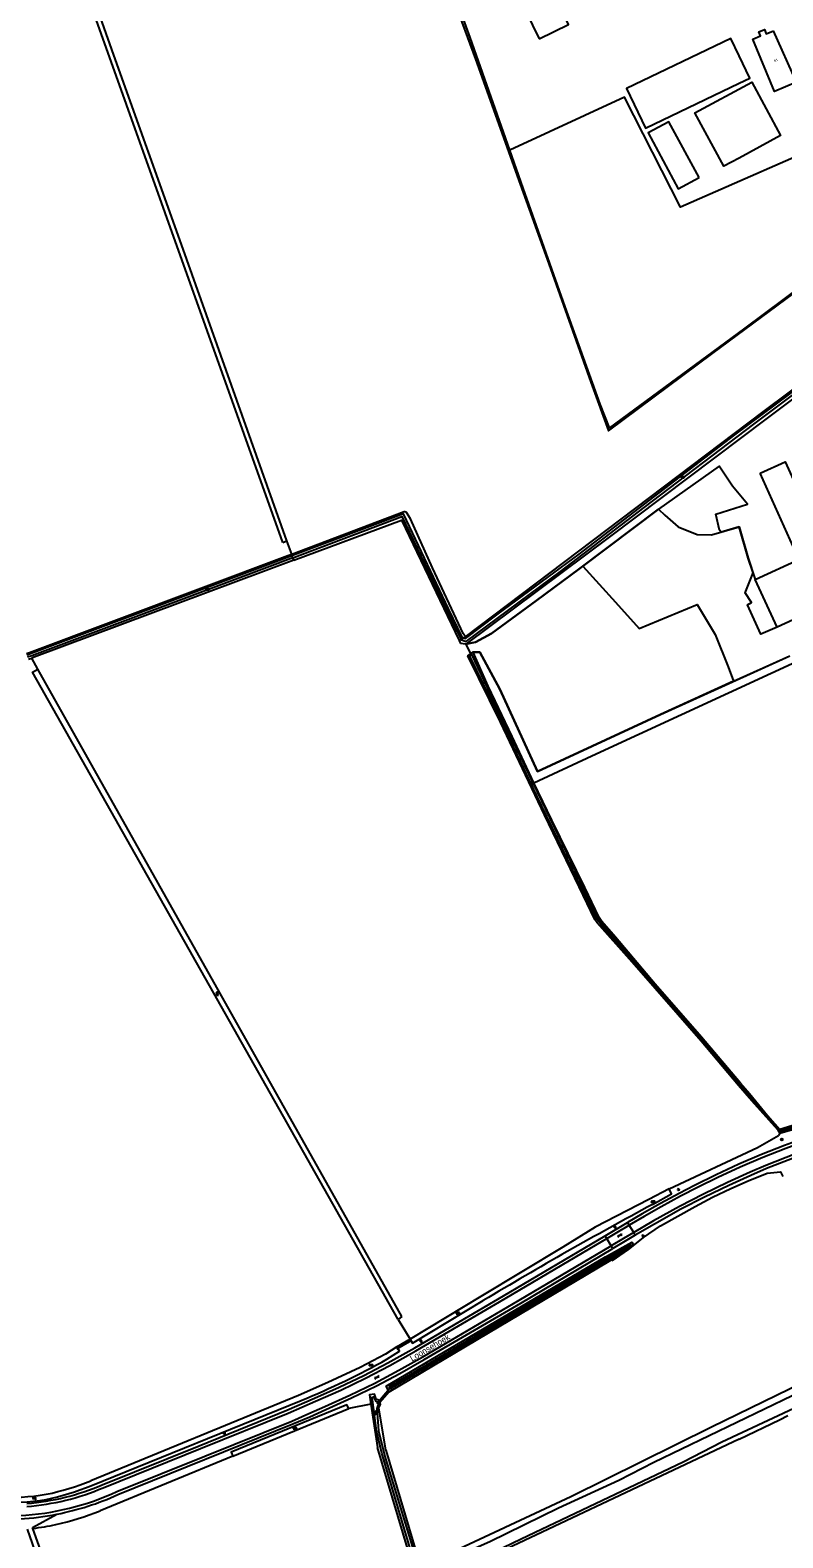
# Model space of a CAD drawing. Extents: x 134297 to 137000, y 403500 to 406000.
# Drawn here: x 135711 to 136018, y 404322 to 404935 of the extents above; entities that cross this region are included whole.
import ezdxf

# ---------------------------------------------------------------- set-up
doc = ezdxf.new("R2010")
doc.units = 0
for name, color, linetype in [('gg-afsc-erfafscheiding', 7, 'Continuous'), ('gg-afsc-lijn draadraster', 7, 'Continuous'), ('gg-anno-huisnummerreeks BGT', 7, 'Continuous'), ('gg-anno-openbare ruimte label', 7, 'Continuous'), ('gg-bbg-gedigitaliseerde bebouwing', 7, 'Continuous'), ('gg-bbg-gedigitaliseerde bijgebouw', 7, 'Continuous'), ('gg-bbg-hoofdgebouw', 7, 'Continuous'), ('gg-bbg-open loods', 7, 'Continuous'), ('gg-knt-bronhoudergrens', 7, 'Continuous'), ('gg-knt-onverhard', 7, 'Continuous'), ('gg-knt-verharding', 7, 'Continuous'), ('gg-knt-verharding nz', 7, 'Continuous'), ('gg-kntw-bovenkant insteek waterloop', 7, 'Continuous'), ('gg-kntw-greppel-droge sloot', 7, 'Continuous'), ('gg-kntw-waterlijn', 7, 'Continuous'), ('gg-kwrk-duiker nz buis', 7, 'Continuous'), ('gt-grn-groengrens', 7, 'Continuous'), ('gt-grn-vlakafsluiter', 7, 'Continuous'), ('gt-symb-boom', 7, 'Continuous'), ('gt-symb-gesloten verharding', 7, 'Continuous'), ('gt-symb-groenvak', 7, 'Continuous'), ('gt-symb-lichtmast', 7, 'Continuous'), ('gt-symb-watersymbool', 7, 'Continuous')]:
    doc.layers.add(name, color=color, linetype=linetype)

# ---------------------------------------------------------------- blocks, each defined once
blk = doc.blocks.new('gt0-WA')
at = {"layer": 'gt-symb-watersymbool'}
for centre, start, end in [((-0.32, 0.02), 28.07249, 151.92751), ((0.43, 0.42), 208.07248, 331.92751), ((-0.32, -0.43), 28.07249, 151.92751), ((0.43, -0.03), 208.07248, 331.92751)]:
    blk.add_arc(centre, 0.425, start, end, dxfattribs=at)
blk = doc.blocks.new('gt0-GRVAK')
at = {"layer": 'gt-symb-groenvak'}
for p, q in [((-0.11, 0.19), (-0.23, 0.24)), ((-0.18, 0.15), (0.09, 0.15)), ((-0.09, 0.21), (-0.16, 0.32)), ((-0.05, 0.21), (-0.05, 0.39)), ((0, 0.21), (0.06, 0.32)), ((0.01, 0.19), (0.13, 0.24)), ((0.26, -0.05), (0.2, 0.06)), ((0.3, -0.05), (0.3, 0.13)), ((0.35, -0.05), (0.41, 0.06)), ((-0.24, -0.23), (-0.36, -0.18)), ((-0.32, -0.26), (-0.05, -0.26)), ((-0.23, -0.21), (-0.29, -0.09)), ((-0.18, -0.2), (-0.18, -0.02)), ((-0.14, -0.21), (-0.07, -0.09)), ((-0.12, -0.23), (0, -0.18)), ((0.24, -0.07), (0.12, -0.02)), ((0.17, -0.11), (0.44, -0.11)), ((0.37, -0.07), (0.49, -0.02))]:
    blk.add_line(p, q, dxfattribs=at)
blk = doc.blocks.new('gt0-BOOM')
at = {"layer": 'gt-symb-boom'}
for radius in [0.4, 0.2]:
    blk.add_circle((0, 0), radius, dxfattribs=at)
blk = doc.blocks.new('gt0-LMAST')
at = {"layer": 'gt-symb-lichtmast'}
for p, q in [((-0.18, 0.17), (-0.45, 0.44)), ((-0.01, 0.25), (-0.01, 0.62)), ((0.17, 0.17), (0.44, 0.44)), ((-0.26, 0), (-0.63, 0)), ((-0.18, -0.18), (-0.45, -0.45)), ((-0.01, -0.25), (-0.01, -0.63)), ((0.44, -0.45), (0.17, -0.18)), ((0.24, 0), (0.62, 0))]:
    blk.add_line(p, q, dxfattribs=at)
blk.add_circle((-0.01, 0), 0.25, dxfattribs=at)
blk = doc.blocks.new('gt0-GESVH1')
at = {"layer": 'gt-symb-gesloten verharding'}
for p, q in [((-0.99, -0.26), (0.01, 0.24)), ((0.01, -0.26), (-0.99, 0.24)), ((0.01, 0.24), (1.01, -0.26)), ((1.01, 0.24), (0.01, -0.26))]:
    blk.add_line(p, q, dxfattribs=at)

msp = doc.modelspace()

# ---------------------------------------------------------------- linework, layer by layer
at = {"layer": 'gg-afsc-erfafscheiding'}
for points in [[(135957.54, 404441.04), (135961.12, 404443.87), (135967.97, 404448.6), (135982.07, 404456.53), (135989.17, 404460.21), (135996.7, 404463.84), (136003.68, 404466.94), (136011.43, 404470.04), (136016.83, 404470.55), (136017.86, 404468.65)], [(135948.32, 404434.33), (135954.91, 404438.96), (135957.54, 404441.04)]]:
    msp.add_lwpolyline(points, dxfattribs=at)
at = {"layer": 'gg-afsc-lijn draadraster'}
for points in [[(135888.71, 404685.35), (135892.64, 404686.27), (135899.22, 404689.69), (135917.56, 404703.22), (135934.71, 404715.88), (135967.23, 404740.38), (135969.71, 404737.86), (135975.2, 404733.09), (135982.87, 404730), (135988.76, 404729.87), (136000.04, 404733.1), (136003.69, 404720.35), (136006.61, 404711.76)], [(135891.63, 404682.14), (135894.48, 404682.14), (135902.55, 404667.01), (135917.87, 404633.54), (135968.02, 404656.71), (136020.74, 404680.69)]]:
    msp.add_lwpolyline(points, dxfattribs=at)
at = {"layer": 'gg-bbg-gedigitaliseerde bebouwing'}
for p, q in [((136015.5, 404692.32), (136006.61, 404711.76)), ((136037.55, 404702.41), (136015.5, 404692.32))]:
    msp.add_line(p, q, dxfattribs=at)
for points in [[(136023.43, 404914.15), (136014.49, 404910.31), (136005.64, 404931.74), (136008.69, 404933), (136007.99, 404934.68), (136010.3, 404935.64), (136011.03, 404933.86), (136014.05, 404935.11)], [(136006.61, 404711.76), (136043.23, 404728.51), (136050.86, 404711.82)]]:
    msp.add_lwpolyline(points, dxfattribs=at)
at = {"layer": 'gg-bbg-gedigitaliseerde bijgebouw'}
for points in [[(135918.59, 404931.82), (135930.48, 404937.6), (135922.33, 404954.36), (135910.45, 404948.58), (135918.59, 404931.82)], [(136000, 404913.71), (136004.38, 404915.8), (136000, 404924.86), (135996.62, 404931.93), (135954.14, 404911.6), (135961.86, 404895.46), (136000, 404913.71)], [(136000, 404883.29), (135993.79, 404879.94), (135982.05, 404901.68), (136005.16, 404914.15), (136016.9, 404892.42), (136000, 404883.29)], [(135983.69, 404875.3), (135971.4, 404898.07), (135962.95, 404893.51), (135975.24, 404870.74), (135983.69, 404875.3)]]:
    msp.add_lwpolyline(points, dxfattribs=at)
at = {"layer": 'gg-bbg-hoofdgebouw'}
msp.add_line((136023.43, 404914.15), (136014.05, 404935.11), dxfattribs=at)
at = {"layer": 'gg-bbg-open loods'}
msp.add_lwpolyline([(136008.58, 404755.04), (136018.79, 404759.66), (136032.3, 404729.75), (136022.09, 404725.14), (136008.58, 404755.04)], dxfattribs=at)
at = {"layer": 'gg-knt-bronhoudergrens'}
for p, q in [((135817.78, 404721.99), (135815.85, 404727.41)), ((135888.71, 404685.35), (135890.62, 404681.43)), ((135714.42, 404675.26), (135711.91, 404679.73)), ((135997.78, 404670.3), (136020.74, 404680.69)), ((135861.09, 404410.43), (135866.07, 404402.51))]:
    msp.add_line(p, q, dxfattribs=at)
for points in [[(136015.5, 404692.32), (136008.81, 404689.4), (136003.4, 404701.35), (136005.13, 404702.37), (136002.48, 404706.25), (136005.71, 404714.41), (136005.71, 404714.41), (136003.69, 404720.35), (136000.04, 404733.1), (135992.7, 404731), (135992.06, 404731.79), (135990.52, 404738.33), (136003.4, 404742.41), (135997.27, 404749.77), (135991.96, 404757.84), (135967.23, 404740.38), (135936.4, 404717.16)], [(135916.45, 404629), (135940.08, 404639.92), (136124.35, 404724.9)], [(135936.4, 404717.16), (135934.71, 404715.88), (135917.56, 404703.22), (135899.22, 404689.69), (135892.64, 404686.27), (135888.71, 404685.35)], [(135936.4, 404717.16), (135949.67, 404702.47), (135959.37, 404691.75), (135982.97, 404701.55), (135990.22, 404689.3), (135995.63, 404676.22), (135997.78, 404670.3)], [(135997.78, 404670.3), (135968.02, 404656.71), (135917.87, 404633.54), (135902.55, 404667.01), (135894.48, 404682.14), (135891.63, 404682.14)], [(135971.54, 404463.67), (136007.56, 404480.54), (136016.01, 404485.35)]]:
    msp.add_lwpolyline(points, dxfattribs=at)
at = {"layer": 'gg-knt-onverhard'}
for p, q in [((135712.18, 404325.82), (135722.09, 404331.22)), ((135722.25, 404291.15), (135710.12, 404325.06)), ((135712.31, 404325.45), (135712.18, 404325.82)), ((135724.39, 404292.09), (135712.31, 404325.45))]:
    msp.add_line(p, q, dxfattribs=at)
at = {"layer": 'gg-knt-verharding'}
for p, q in [((135945.45, 404444.58), (135954.61, 404449.98)), ((135955.27, 404448.86), (135954.61, 404449.98)), ((135957.08, 404445.86), (135955.27, 404448.86)), ((135957.74, 404444.76), (135957.08, 404445.86)), ((135946.12, 404443.45), (135945.45, 404444.58)), ((135947.92, 404440.47), (135946.12, 404443.45)), ((135948.58, 404439.37), (135947.92, 404440.47))]:
    msp.add_line(p, q, dxfattribs=at)
for points in [[(136197.49, 404535.45), (136195.13, 404534.58), (136162.9, 404522.97), (136127.36, 404510.1), (136113.62, 404505.3), (136099.76, 404500.63), (136086.34, 404496.28), (136076.86, 404493.32), (136066.07, 404490.19), (136055.56, 404487.24), (136045.09, 404484), (136034.7, 404480.64), (136023.56, 404476.68), (136011.23, 404471.9), (136004.74, 404469.15), (135995.87, 404465.09), (135985.92, 404460.27), (135976.35, 404455.35), (135965.54, 404449.33), (135957.74, 404444.76)], [(136108.2, 404509.87), (136098.64, 404506.63), (136084.48, 404502.05), (136070.65, 404497.79), (136060.14, 404494.87), (136049.92, 404491.85), (136039.52, 404488.61), (136028.95, 404485.07), (136018.55, 404481.26), (136009.16, 404477.58), (135999.86, 404473.65), (135990.66, 404469.37), (135981.82, 404465.02), (135975.54, 404461.77), (135967.96, 404457.68), (135960.58, 404453.48), (135954.61, 404449.98)], [(135740.54, 404343.18), (135780.12, 404359.11), (135815.76, 404373.51), (135827.08, 404378.39), (135837.06, 404382.9), (135847.16, 404387.74), (135856.95, 404392.79), (135867.93, 404398.96), (135904.12, 404420.16), (135945.45, 404444.58)], [(135746.93, 404339.17), (135818.29, 404367.99), (135825.14, 404370.92), (135831.67, 404373.79), (135842.2, 404378.57), (135852.33, 404383.49), (135861.87, 404388.55), (135871.74, 404394.13), (135911.08, 404417.16), (135948.58, 404439.37)], [(135957.74, 404444.76), (135953.56, 404442.31), (135948.58, 404439.37)]]:
    msp.add_lwpolyline(points, dxfattribs=at)
for centre, radius, start, end in [((135702.17, 404432.43), 97.15, 274.53281, 293.26455), ((135700.9, 404440.23), 111.05, 281.00014, 294.49037), ((135700.86, 404440.33), 111.16, 273.17752, 281.0098)]:
    msp.add_arc(centre, radius, start, end, dxfattribs=at)
at = {"layer": 'gg-knt-verharding nz'}
for points in [[(136197.15, 404540.4), (136161.45, 404527.53), (136124.76, 404514.25), (136111.52, 404509.6), (136099.13, 404505.43), (136084.9, 404500.78), (136071.52, 404496.67), (136060.9, 404493.69), (136050.35, 404490.61), (136039.81, 404487.34), (136029.4, 404483.84), (136019.03, 404480.06), (136009.73, 404476.4), (136000.5, 404472.45), (135991.4, 404468.23), (135983.33, 404464.29), (135976.2, 404460.63), (135968.25, 404456.35), (135961.29, 404452.4), (135955.27, 404448.86)], [(136197.38, 404536.83), (136126.86, 404511.31), (136112.69, 404506.32), (136099.4, 404501.86), (136086.05, 404497.55), (136076.48, 404494.56), (136065.87, 404491.48), (136055.28, 404488.5), (136044.76, 404485.25), (136034.33, 404481.86), (136023.04, 404477.86), (136010.9, 404473.14), (136004.49, 404470.44), (135995.36, 404466.29), (135985.46, 404461.47), (135975.71, 404456.46), (135965.21, 404450.62), (135957.08, 404445.86)], [(135946.12, 404443.45), (135950.24, 404445.9), (135955.27, 404448.86)], [(135957.08, 404445.86), (135952.93, 404443.43), (135947.92, 404440.47)], [(135741.02, 404342), (135780.57, 404357.93), (135816.37, 404372.36), (135827.53, 404377.18), (135837.73, 404381.77), (135847.78, 404386.58), (135857.7, 404391.73), (135868.35, 404397.7), (135904.76, 404419.01), (135939.21, 404439.35), (135946.12, 404443.45)], [(135746.53, 404340.42), (135782.41, 404354.84), (135817.78, 404369.15), (135824.75, 404372.15), (135831.32, 404375.02), (135841.52, 404379.66), (135851.6, 404384.58), (135861.4, 404389.8), (135871.13, 404395.29), (135910.38, 404418.29), (135947.92, 404440.47)]]:
    msp.add_lwpolyline(points, dxfattribs=at)
for centre, radius, start, end in [((135702.21, 404432.79), 98.73, 274.43036, 293.14082), ((135701.35, 404438.77), 108.23, 272.98533, 294.67638)]:
    msp.add_arc(centre, radius, start, end, dxfattribs=at)
at = {"layer": 'gg-kntw-bovenkant insteek waterloop'}
for p, q in [((135817.78, 404721.99), (135863.53, 404739.35)), ((135817.78, 404721.99), (135817.64, 404721.95)), ((135886.02, 404686.91), (135886.6, 404685.71)), ((135888.71, 404685.35), (135886.6, 404685.71)), ((135710.57, 404679.25), (135711.91, 404679.73)), ((135891.63, 404682.14), (135890.62, 404681.43)), ((135862.58, 404411.68), (135714.42, 404675.26)), ((136015.74, 404487.62), (136016.61, 404486.32)), ((135971.54, 404463.67), (135963.3, 404459.3)), ((135894.87, 404419.83), (135866.07, 404402.51)), ((135862.58, 404411.68), (135861.09, 404410.43)), ((135860.59, 404399.33), (135856.04, 404396.3)), ((135820.6, 404379.54), (135736.01, 404344.85)), ((135735.97, 404342.78), (135821.69, 404377.57)), ((135793.78, 404354.9), (135840.99, 404374.19)), ((135850.06, 404375.98), (135852.72, 404358.41)), ((136000, 404361.71), (136016.41, 404369.66)), ((136016.41, 404369.66), (136019.93, 404371.37)), ((135856.14, 404357.26), (135870.01, 404310.73))]:
    msp.add_line(p, q, dxfattribs=at)
for points in [[(135883.81, 404947.37), (135892.62, 404923.5), (135909.58, 404876.1), (135922.55, 404840.24), (135939.63, 404792.04), (135946.81, 404772.2), (135989.29, 404803.84), (136051.9, 404850.06)], [(135906.64, 404886.48), (135890.46, 404932.4), (135884.87, 404947.76)], [(136051.9, 404850.06), (136051.5, 404850.62), (136001.81, 404813.68), (135947.26, 404773.45), (135943.41, 404783.07), (135929.19, 404822.74), (135912.06, 404871.08), (135906.64, 404886.48)], [(135888.64, 404688.41), (136009.8, 404779.91), (136075.84, 404829.22)], [(136077.07, 404826.68), (136011.46, 404777.41), (135947.05, 404728.91), (135888.71, 404685.35)], [(135818.63, 404719.53), (135862.53, 404735.9), (135886.02, 404686.91)], [(135888.64, 404688.41), (135887.6, 404689.79), (135875.12, 404716.41), (135866.2, 404736.36), (135864.55, 404739.03), (135863.53, 404739.35)], [(135817.64, 404721.95), (135816.14, 404721.38), (135711.01, 404681.86), (135709.72, 404681.43)], [(135818.63, 404719.53), (135712.86, 404680.07), (135711.91, 404679.73)], [(135999.83, 404505.8), (135984.5, 404523.77), (135956.43, 404555.89), (135942.15, 404572.01), (135941.32, 404573.36), (135934.86, 404586.61), (135920.78, 404615.89), (135902.8, 404653.64), (135889.49, 404680.65), (135890.62, 404681.43)], [(135916.45, 404629), (135907.56, 404647.81), (135897.76, 404668.29), (135891.63, 404682.14)], [(135861.09, 404410.43), (135712.21, 404674.03), (135714.42, 404675.26)], [(136000.6, 404506.74), (135984.69, 404525.37), (135965.77, 404546.93), (135949.72, 404566.06), (135944.07, 404572.56), (135943.03, 404574.15), (135937.18, 404586.34), (135923.68, 404613.72), (135916.45, 404629)], [(136015.74, 404487.62), (136005.19, 404499.51), (135999.83, 404505.8)], [(136000.6, 404506.74), (136004.27, 404502.44), (136011.6, 404493.47), (136016.62, 404487.88)], [(136016.61, 404486.32), (136052.67, 404496.71), (136063.77, 404500)], [(136057.39, 404500), (136046.29, 404496.71), (136035.18, 404493.49), (136016.62, 404487.88)], [(136232.4, 404483.42), (136229.09, 404483.22), (136211.35, 404474.91), (136179.65, 404459.33), (136143.55, 404441.91), (136089.18, 404415.38), (136050.09, 404396.55), (136020.57, 404382.16), (135988.75, 404366.64), (135931.54, 404338.35), (135877.73, 404313.16)], [(135963.3, 404459.3), (135941.33, 404448.06), (135928.25, 404439.96), (135894.87, 404419.83)], [(135964.72, 404457.32), (135972.46, 404461.64), (135971.54, 404463.67)], [(135857.5, 404381.02), (135856.24, 404383.31), (135945.62, 404435.99), (135956.35, 404441.9), (135957.06, 404440.85)], [(135857.5, 404381.02), (135951.42, 404436.76), (135957.06, 404440.85)], [(135866.07, 404402.51), (135866.98, 404400.84), (135895.78, 404418.15)], [(135856.58, 404394.29), (135861.71, 404397.54), (135860.59, 404399.33)], [(135856.04, 404396.3), (135845.68, 404390.96), (135832.52, 404384.79), (135820.6, 404379.54)], [(135853.71, 404376.7), (135853.5, 404377.57), (135852.23, 404378.07), (135851.53, 404380.11), (135849.47, 404379.86), (135850.06, 404375.98)], [(135840.99, 404374.19), (135840.26, 404375.75), (135793.19, 404356.51), (135793.78, 404354.9)], [(135856.14, 404357.26), (135853.25, 404374.45), (135853.93, 404375.83), (135853.71, 404376.7)], [(136000, 404361.71), (135880.94, 404305.58), (135878.61, 404307.31), (135876.7, 404311.45), (135877.73, 404313.16)], [(135870.01, 404310.73), (135867.31, 404309.61), (135852.72, 404358.41)]]:
    msp.add_lwpolyline(points, dxfattribs=at)
for centre, radius, start, end in [((136796.91, 402911.99), 1755.16, 118.3033, 120.89196), ((135693.81, 404689.21), 336.86, 292.31094, 298.89416), ((135704.18, 404415.49), 77.37, 250.13401, 280.16042), ((135696.53, 404439.94), 104.86, 281.69302, 292.09406), ((135696.57, 404442.01), 104.86, 281.69302, 292.09406), ((135703.54, 404415.03), 79.07, 250.3395, 280.37058)]:
    msp.add_arc(centre, radius, start, end, dxfattribs=at)
at = {"layer": 'gg-kntw-greppel-droge sloot'}
for q in [(135721.84, 404985.18), (135815.85, 404727.41)]:
    msp.add_line((135814.21, 404726.79), q, dxfattribs=at)
msp.add_lwpolyline([(135815.85, 404727.41), (135772.93, 404848.03), (135745.3, 404925.2), (135724.03, 404985.56)], dxfattribs=at)
at = {"layer": 'gg-kntw-waterlijn'}
for points in [[(135886.83, 404687.37), (135886.94, 404687.16), (135888.8, 404686.46), (135927.31, 404715.02), (135961.33, 404741.08), (136005.98, 404775), (136059.04, 404814.65), (136071.15, 404823.52), (136076.55, 404827.75)], [(135887.78, 404687.92), (135888.53, 404687.75), (135901.38, 404697.31), (135934.87, 404722), (135998.34, 404770.55), (136076.18, 404828.52)], [(135887.78, 404687.92), (135887.4, 404688.01), (135881.62, 404699.74), (135863.31, 404738.4), (135817.87, 404721.38)], [(135818.22, 404720.54), (135862.7, 404737.4), (135882.82, 404695.13), (135886.83, 404687.37)], [(135817.87, 404721.38), (135723.6, 404686.07), (135709.89, 404680.98)], [(135818.22, 404720.54), (135797.39, 404712.64), (135711.87, 404680.62), (135710.23, 404680.11)], [(136000.05, 404506.07), (135985.86, 404522.72), (135952.19, 404561.37), (135944.49, 404570.16), (135942.3, 404573.14), (135936.29, 404585.2), (135917.69, 404623.61), (135898.57, 404663.48), (135890.32, 404680.57), (135891.08, 404681.2), (135904.09, 404653.8), (135933.18, 404593.08), (135942.65, 404573.73), (135944.11, 404571.66), (135979.04, 404531.32), (135989.04, 404519.72), (136000.35, 404506.45)], [(136016.73, 404487.35), (136022.35, 404489.09), (136076.78, 404505.34), (136106.63, 404514.78), (136106.73, 404514.04), (136081.04, 404505.97), (136016.77, 404486.75)], [(136016.77, 404486.75), (136014.83, 404489.08), (136000.05, 404506.07)], [(136000.35, 404506.45), (136005.99, 404499.83), (136011.37, 404493.32), (136016.73, 404487.35)], [(135884.16, 404313.75), (135898.53, 404320.11), (135926.42, 404333.8), (135951.05, 404345.14), (135965.34, 404352.44), (136021.67, 404379.51), (136084.87, 404410.41), (136126.48, 404430.96), (136169.18, 404451.47), (136204.36, 404468.59), (136233.6, 404482.32), (136235.31, 404482.99), (136237.37, 404483.02), (136237.66, 404482.34)], [(135885.33, 404308.76), (135911.22, 404321.24), (135977.2, 404352.57), (135993.05, 404360.74), (136022.28, 404374.43), (136052.47, 404388.81), (136081.4, 404402.63), (136112.63, 404418.58), (136144.64, 404434.05), (136190.99, 404456.03), (136224.47, 404472.11), (136236.59, 404477.67), (136237.28, 404476.11)], [(135857.42, 404383.07), (135871.82, 404391.44), (135955.81, 404441.14), (135956.05, 404440.74), (135950.12, 404436.93), (135930.56, 404425.27), (135857.86, 404382.2), (135857.42, 404383.07)], [(135867.78, 404311.24), (135854.48, 404356.01), (135852.34, 404365.16), (135850.49, 404378.87), (135851.08, 404378.95), (135851.86, 404377.38), (135852.68, 404376.98), (135853.09, 404376.23), (135852.4, 404374.19), (135853.16, 404365.1), (135855.75, 404354.71), (135868.92, 404311.61), (135867.78, 404311.24)]]:
    msp.add_lwpolyline(points, dxfattribs=at)
at = {"layer": 'gg-kwrk-duiker nz buis'}
for p, q in [((135860.66, 404398.53), (135866.72, 404402)), ((135857.65, 404382.25), (135852.4, 404376.19))]:
    msp.add_line(p, q, dxfattribs=at)
at = {"layer": 'gt-grn-groengrens'}
for p, q in [((136016.61, 404486.32), (136016.01, 404485.35)), ((135957.54, 404441.04), (135957.06, 404440.85)), ((135865.27, 404402.05), (135866.07, 404402.51)), ((135860.59, 404399.33), (135865.27, 404402.05)), ((135857.5, 404381.02), (135853.71, 404376.7)), ((135850.06, 404375.98), (135840.99, 404374.19)), ((135793.78, 404354.9), (135739.76, 404332.65))]:
    msp.add_line(p, q, dxfattribs=at)
msp.add_lwpolyline([(136045.86, 404893.83), (136043.08, 404892.65), (135976.15, 404863.29), (135953.37, 404908.11), (135906.64, 404886.48)], dxfattribs=at)
for centre, radius, start, end in [((135697.38, 404437.81), 113.39, 282.37563, 291.95178), ((135703.49, 404405.02), 80.06, 276.33033, 283.13366)]:
    msp.add_arc(centre, radius, start, end, dxfattribs=at)
at = {"layer": 'gt-grn-vlakafsluiter'}
for p, q in [((135817.64, 404721.95), (135817.87, 404721.38)), ((135818.22, 404720.54), (135817.87, 404721.38)), ((135818.63, 404719.53), (135818.22, 404720.54)), ((135886.83, 404687.37), (135886.02, 404686.91)), ((135886.83, 404687.37), (135887.78, 404687.92)), ((135887.78, 404687.92), (135888.64, 404688.41)), ((135999.83, 404505.8), (136000.05, 404506.07)), ((136000.05, 404506.07), (136000.35, 404506.45)), ((136000.35, 404506.45), (136000.6, 404506.74)), ((136016.61, 404486.32), (136016.77, 404486.75)), ((136016.73, 404487.35), (136016.62, 404487.88)), ((136016.77, 404486.75), (136016.73, 404487.35))]:
    msp.add_line(p, q, dxfattribs=at)

# ---------------------------------------------------------------- block references
at = {"layer": 'gt-symb-boom'}
msp.add_blockref('gt0-BOOM', (136017.43, 404483.72), dxfattribs=at)
at = {"layer": 'gt-symb-gesloten verharding'}
for p, rotation in [((135951.41, 404444.72), 30.128600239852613), ((135852.46, 404386.95), 28.23090182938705)]:
    msp.add_blockref('gt0-GESVH1', p, dxfattribs=dict(at, rotation=rotation))
at = {"layer": 'gt-symb-groenvak'}
for p in [(135975.33, 404463.42), (135960.88, 404444.66)]:
    msp.add_blockref('gt0-GRVAK', p, dxfattribs=at)
at = {"layer": 'gt-symb-lichtmast'}
for p in [(135949.52, 404448.05), (135870.48, 404401.67), (135790.27, 404364.22)]:
    msp.add_blockref('gt0-LMAST', p, dxfattribs=at)
at = {"layer": 'gt-symb-watersymbool'}
for p, rotation in [((135892.43, 404925.39), 109.99289397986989), ((135977.04, 404753.3), 36.950127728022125), ((135783.35, 404707.78), -159.51770311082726), ((135915.48, 404628.59), 115.6678751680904), ((135787.47, 404542.97), 119.46071361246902), ((135984.71, 404524.43), -49.504417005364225), ((135964.89, 404458.42), 38.99099403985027), ((135945.67, 404434.71), 38.99099404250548), ((135885.39, 404413.02), 38.99099404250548), ((135850.03, 404391.85), 33.00706175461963), ((135873.3, 404391.98), 38.99099404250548), ((135852.09, 404372.43), 104.00844348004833), ((135819.06, 404366.18), 33.00706175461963), ((135713.01, 404337.64), 16.98473253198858)]:
    msp.add_blockref('gt0-WA', p, dxfattribs=dict(at, rotation=rotation))

# ---------------------------------------------------------------- texts
at = {"layer": 'gg-anno-huisnummerreeks BGT'}
msp.add_text('61', height=1, rotation=24.1, dxfattribs=at).set_placement((136014.55, 404922.31))
at = {"layer": 'gg-anno-openbare ruimte label'}
msp.add_text('Loonsehoek', height=2.5, rotation=30.7, dxfattribs=at).set_placement((135866.84, 404393.31))

doc.saveas('drawing.dxf')
